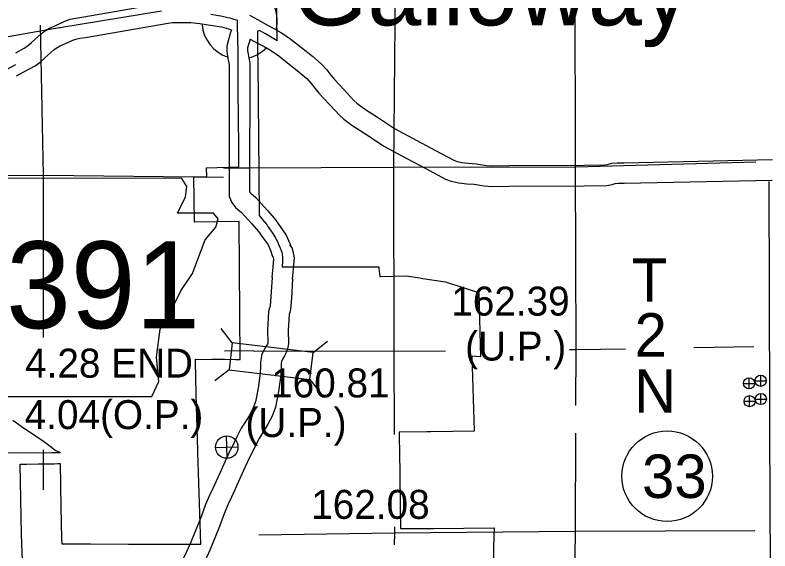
# Model space of a CAD drawing. Extents: x 1127717 to 1741049, y 2026793 to 2244711.
# Drawn here: x 1242222 to 1247728, y 2133375 to 2137280 of the extents above; entities that cross this region are included whole.
import ezdxf

# ---------------------------------------------------------------- set-up
doc = ezdxf.new("R2010")
doc.units = 0
for name, color, linetype in [('10', 7, 'Continuous'), ('15', 7, 'Continuous'), ('2', 7, 'Continuous'), ('20', 7, 'Continuous'), ('21', 7, 'Continuous'), ('24', 7, 'Continuous'), ('25', 7, 'Continuous'), ('26', 7, 'Continuous'), ('27', 7, 'Continuous'), ('30', 7, 'Continuous'), ('5', 7, 'Continuous'), ('58', 7, 'Continuous'), ('6', 7, 'Continuous')]:
    doc.layers.add(name, color=color, linetype=linetype)

msp = doc.modelspace()

# ---------------------------------------------------------------- linework, layer by layer
at = {"layer": '10'}
for points in [[(1243799.9, 2137173.2), (1243794.3, 2137152.9), (1243770.9, 2137074.7), (1243766.7, 2137050), (1243766.2, 2137021.9), (1243768.5, 2136998.8), (1243772.1, 2136979.4), (1243783.7, 2136915.3)], [(1243936.6, 2137105.4), (1243917.3, 2137040.6), (1243916.5, 2137035.9), (1243916.3, 2137027.9), (1243917.1, 2137020), (1243919.6, 2137006.5), (1243933.7, 2136928.7)], [(1243933.7, 2136928.7), (1243932.5, 2135992)], [(1243783.7, 2136915.3), (1243782.5, 2135957.4)], [(1243932.5, 2135992), (1243932.4, 2135992.3), (1243940.7, 2135981.2), (1243977.1, 2135949.5), (1244060.5, 2135858.8), (1244114.3, 2135797.2), (1244156.6, 2135739.2), (1244200, 2135677.1), (1244226.1, 2135614.4), (1244235.4, 2135589.3)], [(1243782.5, 2135957.4), (1243804, 2135913.5), (1243830.3, 2135878.5), (1243872.2, 2135841.9), (1243948.8, 2135758.7), (1243997, 2135703.5), (1244034.5, 2135652), (1244067.8, 2135604.5), (1244086.5, 2135559.5), (1244098.2, 2135528)], [(1244246.4, 2135356.2), (1244253.3, 2135430.6), (1244259.2, 2135510.7), (1244252.8, 2135548.2), (1244242, 2135584), (1244226.6, 2135606.1)], [(1244097, 2135370.1), (1244103.8, 2135443.1), (1244108.3, 2135503.5), (1244106.5, 2135513.8), (1244105.3, 2135517.8), (1244098.2, 2135528)], [(1244096.9, 2135368.2), (1244087.4, 2135228.9), (1244081.5, 2135157.3), (1244081.3, 2135156.2), (1244074.9, 2135140.9), (1244070.7, 2135116.2), (1244063.1, 2134986.6), (1244065.9, 2134894.4), (1244064.8, 2134888.7), (1244062.3, 2134882.4), (1244054.5, 2134866.7), (1244039.6, 2134840.7), (1244021.8, 2134808), (1244016.7, 2134780.2), (1244013, 2134749.3), (1244011.8, 2134720.8)], [(1244246.5, 2135358), (1244237, 2135217.6), (1244230.3, 2135136.2), (1244225.4, 2135112), (1244219.9, 2135098.9), (1244213.2, 2134984.4), (1244216.3, 2134883.1), (1244209.8, 2134847.4), (1244199.4, 2134821.1), (1244186.8, 2134795.8), (1244170.6, 2134767.6), (1244165, 2134757.3), (1244162.6, 2134737.2), (1244161.6, 2134714.4)], [(1244011.8, 2134720.8), (1244009.6, 2134669.8), (1243994.1, 2134560.9), (1243975.7, 2134461.3), (1243959.4, 2134417.6), (1243935.6, 2134371.4), (1243904.6, 2134321.3), (1243872, 2134269.3), (1243841.4, 2134211.4), (1243797.1, 2134119.5)], [(1244161.6, 2134714.4), (1244159.2, 2134656), (1244142.2, 2134536.7), (1244120.8, 2134421.2), (1244096.8, 2134356.8), (1244066.2, 2134297.5), (1244031.9, 2134242), (1244002, 2134194.3), (1243975.3, 2134143.7), (1243932.2, 2134054.3)], [(1243796.5, 2134118.3), (1243764.8, 2134049.6), (1243714.8, 2133942.5), (1243687.8, 2133882.9), (1243663.1, 2133830.1), (1243636.1, 2133769.8), (1243611.9, 2133713.8), (1243590.8, 2133656.1), (1243573.1, 2133605.1), (1243504.7, 2133439.6), (1243456.7, 2133335.2), (1243439.3, 2133301.6), (1243428.4, 2133270.6), (1243412, 2133204.1), (1243332.4, 2132858.6)], [(1243932.7, 2134055.5), (1243900.9, 2133986.5), (1243851.1, 2133879.9), (1243824.1, 2133820.1), (1243799.5, 2133767.6), (1243773.4, 2133709.4), (1243751.3, 2133658.2), (1243732.1, 2133605.8), (1243713.4, 2133551.8), (1243642.2, 2133379.6), (1243591.5, 2133269.3), (1243577.4, 2133242.1), (1243572.4, 2133227.7), (1243557.9, 2133169.2), (1243485.6, 2132855.4)]]:
    msp.add_lwpolyline(points, dxfattribs=at)
at = {"layer": '15'}
for points in [[(1242228.1, 2137005.3), (1242288.1, 2137037.9), (1242295.6, 2137043.4), (1242309.9, 2137054.3), (1242340.9, 2137080.9), (1242411, 2137142.8), (1242436.4, 2137161.8), (1242474, 2137185.2), (1242527.7, 2137209.9), (1242585.3, 2137234.9), (1242622.7, 2137249.3), (1242665.9, 2137258.2), (1242709.8, 2137265.5), (1243312.7, 2137368.1), (1243354.8, 2137376), (1243395.8, 2137376.8), (1243435.9, 2137376.7), (1243515.2, 2137374.8), (1243587.7, 2137366.3), (1243682.5, 2137353), (1243757.1, 2137342.3), (1243777.3, 2137336.7)], [(1243931.1, 2137279.2), (1243941, 2137274.1), (1244012.1, 2137235), (1244067.2, 2137204.6), (1244109.6, 2137182), (1244160.2, 2137153.9)], [(1242231.6, 2136837.4), (1242280.5, 2136863.1), (1242368.8, 2136911), (1242385.7, 2136923.4), (1242404.4, 2136937.8), (1242439.3, 2136967.8), (1242505.7, 2137026.3), (1242521.2, 2137037.9), (1242545.2, 2137052.9), (1242588.8, 2137072.9), (1242642.3, 2137096.1), (1242665.1, 2137104.9), (1242693.2, 2137110.7), (1242734.7, 2137117.5), (1243339, 2137220.4), (1243370.3, 2137226.3), (1243397.2, 2137226.8), (1243433.9, 2137226.7), (1243504.6, 2137225), (1243568.5, 2137217.5), (1243661.4, 2137204.5), (1243726.4, 2137195.2), (1243779.2, 2137180.6), (1243797.5, 2137174.3)], [(1244160.2, 2137153.9), (1244222.9, 2137112.1), (1244311.3, 2137043.5), (1244391.2, 2136979.4), (1244454.7, 2136924.1), (1244494.6, 2136879.8), (1244524.8, 2136842.6), (1244551.1, 2136810.5), (1244585.9, 2136773.4), (1244623.6, 2136733.3), (1244668.3, 2136685.2), (1244692, 2136658.3), (1244714.9, 2136638.2), (1244764.2, 2136601.4), (1244880.9, 2136525.5), (1244988.9, 2136454.4), (1245151.1, 2136366.3), (1245288.3, 2136293.5), (1245423.3, 2136221.6), (1245446.2, 2136212.7), (1245481.4, 2136204.8), (1245530, 2136200), (1245586.5, 2136196.4), (1245661.2, 2136184.1), (1245706.4, 2136180.7), (1245822.5, 2136182.7), (1246373.5, 2136185.9), (1246521.7, 2136187.5), (1246542.4, 2136192), (1246574.6, 2136200), (1246614.2, 2136203.7), (1246661.3, 2136204.1), (1247745.5, 2136227)], [(1243936.6, 2137105.4), (1243995.7, 2137072.8), (1244037.8, 2137050.3), (1244084.6, 2137024.3)], [(1244079.5, 2137027.4), (1244135.2, 2136990.2), (1244218.4, 2136925.7), (1244295, 2136864.3), (1244349.3, 2136816.9), (1244380.6, 2136782.2), (1244408.5, 2136747.9), (1244438.2, 2136711.6), (1244476.6, 2136670.7), (1244514, 2136630.9), (1244557.1, 2136584.5), (1244586, 2136551.8), (1244620.5, 2136521.5), (1244678.4, 2136478.3), (1244798.8, 2136400), (1244911.7, 2136325.6), (1245080.2, 2136234.2), (1245217.8, 2136161), (1245360.7, 2136085), (1245402.4, 2136068.8), (1245457.6, 2136056.4), (1245518, 2136050.4), (1245569.5, 2136047.2), (1245643.3, 2136035), (1245702.1, 2136030.6), (1245824.3, 2136032.7), (1246374.7, 2136035.9), (1246538.7, 2136037.7), (1246576.5, 2136045.9), (1246599.8, 2136051.7), (1246621.9, 2136053.8), (1246663.5, 2136054.1), (1247745, 2136077)], [(1242020.6, 2136811.2), (1242227.5, 2136920)]]:
    msp.add_lwpolyline(points, dxfattribs=at)
at = {"layer": '2'}
msp.add_lwpolyline([(1247719.9, 2136068.2), (1247726, 2133591.9), (1247745.1, 2132243.6)], dxfattribs=at)
at = {"layer": '20'}
for p, q in [((1243806.5, 2134891.8), (1243724.9, 2134995.6)), ((1244396.2, 2134821), (1244500, 2134902.6)), ((1243782.9, 2134695.2), (1243679.1, 2134613.6)), ((1244372.7, 2134624.4), (1244454.2, 2134520.6))]:
    msp.add_line(p, q, dxfattribs=at)
msp.add_lwpolyline([(1243782.9, 2134695.2), (1244372.7, 2134624.4), (1244396.2, 2134821), (1243806.5, 2134891.8)], close=True, dxfattribs=at)
at = {"layer": '21'}
msp.add_lwpolyline([(1241917.3, 2136090.2), (1241993.5, 2135582.7), (1241959.6, 2134812.9), (1242027.3, 2134770.6), (1242154.2, 2134770.6), (1242154.2, 2134500), (1243220, 2134500), (1243270.8, 2134609.9), (1243253.9, 2134787.6), (1243279.2, 2134990.6), (1243372.3, 2135151.3), (1243431.5, 2135269.7), (1243516.1, 2135396.6), (1243566.8, 2135532), (1243609.1, 2135641.9), (1243685.3, 2135735), (1243702.2, 2135794.2), (1243668.3, 2135836.5), (1243406.1, 2135836.5), (1243465.3, 2135954.9), (1243473.8, 2136031), (1243438.7, 2136089.5)], close=True, dxfattribs=at)
at = {"layer": '24'}
for start, end in [(346.4695, 74.2639), (185.0338, 252.1304), (284.5564, 315.4275)]:
    msp.add_arc((1243859.3, 2137235), 275, start, end, dxfattribs=at)
at = {"layer": '26'}
for p, q in [((1247576.1, 2134555.3), (1247576.1, 2134636.6)), ((1247619.8, 2134614.6), (1247701.1, 2134614.6)), ((1247660.5, 2134574), (1247660.5, 2134655.2)), ((1247535.5, 2134596), (1247616.7, 2134596)), ((1247579.5, 2134425.2), (1247579.5, 2134506.5)), ((1247661.6, 2134440.6), (1247661.6, 2134521.8)), ((1247538.9, 2134465.9), (1247620.1, 2134465.9)), ((1247621, 2134481.2), (1247702.3, 2134481.2)), ((1243768.2, 2134049.9), (1243764.5, 2134212.6)), ((1243685, 2134129.4), (1243847.7, 2134133.1))]:
    msp.add_line(p, q, dxfattribs=at)
for centre, radius in [((1247576.1, 2134596), 40.6), ((1247660.5, 2134614.6), 40.6), ((1247579.5, 2134465.9), 40.6), ((1247661.6, 2134481.2), 40.6), ((1243766.3, 2134131.2), 81.4)]:
    msp.add_circle(centre, radius, dxfattribs=at)
at = {"layer": '27'}
msp.add_circle((1246978.1, 2133919), 330, dxfattribs=at)
at = {"layer": '5'}
for points in [[(1245008.2, 2138758.5), (1244993.1, 2137486.7), (1244981.8, 2136170.8), (1244985.7, 2134830.4), (1244987.2, 2134223.4)], [(1246313.2, 2134435.1), (1246314.3, 2134845.1), (1246309.2, 2136177.5), (1246308.4, 2137514), (1246311.7, 2138782.2)], [(1242429.3, 2134929.9), (1242429.9, 2136113.8), (1242407.7, 2137206.9)], [(1243928.1, 2136165.8), (1244980.3, 2136171.3), (1246311.3, 2136174), (1247623.8, 2136209.8)], [(1243742.4, 2136165.5), (1243928.1, 2136165.8)], [(1242116.8, 2136109.8), (1242431.9, 2136112.4), (1243742.8, 2136098.3)], [(1243960.4, 2134831.9), (1243748.6, 2134831.7)], [(1243960.4, 2134831.9), (1244988.1, 2134831), (1245360.5, 2134834.1)], [(1246264.8, 2134841.7), (1246314.9, 2134842.1), (1246674.9, 2134848.5)], [(1247173.9, 2134857.5), (1247609.4, 2134865.3)], [(1243748.3, 2134770), (1243656.4, 2134770.6)], [(1246292.8, 2132227), (1246310.7, 2133522), (1246312.6, 2134233)], [(1242430.3, 2133819.3), (1242430, 2134111.2)], [(1244000.8, 2133492.3), (1244988.6, 2133507), (1246310.8, 2133519), (1247618.8, 2133523)], [(1244989, 2133549.9), (1244989.1, 2133505), (1244986.7, 2133418.3)]]:
    msp.add_lwpolyline(points, dxfattribs=at)
at = {"layer": '6'}
for points in [[(1244126.3, 2137443.3), (1244132.2, 2137101.1), (1244132.2, 2137099.6), (1244132.3, 2137097.9), (1244132.4, 2137091.9), (1244047.8, 2137142.7), (1244004, 2137168), (1243999.6, 2137166.1), (1243996.5, 2137164.8), (1243993.3, 2137163.3), (1243990.6, 2137162.2), (1243989.2, 2137161.6), (1243990.7, 2137009.4), (1243991.4, 2136933.7), (1243991.5, 2136932.1), (1243991.5, 2136930.4), (1243999.4, 2136119.7), (1244000.5, 2136034.4), (1244000.6, 2136032.9), (1244000.6, 2136031.4), (1244000.9, 2136006.6), (1244000.9, 2136004.7), (1244001, 2136003), (1244001.9, 2135929.8), (1244002.9, 2135857.6), (1244003, 2135849.9), (1244003.4, 2135818.1), (1244003.5, 2135815.8), (1244023.9, 2135791.8), (1244026, 2135789.3), (1244040.9, 2135771.9), (1244042.7, 2135769.9), (1244050.9, 2135760.5), (1244057.9, 2135751.8), (1244060.2, 2135748.9), (1244066.6, 2135739.4), (1244072.9, 2135730.3), (1244094.8, 2135697.3), (1244101.6, 2135686.9), (1244108.1, 2135677), (1244122.8, 2135652.3), (1244126.4, 2135645.7), (1244137.2, 2135625.7), (1244142, 2135616), (1244150.6, 2135594.5), (1244153.2, 2135589), (1244158.3, 2135575.9), (1244158.6, 2135575.1), (1244163, 2135563.3), (1244166.8, 2135552), (1244166.9, 2135551.4), (1244170.4, 2135536.5), (1244172.4, 2135513.8), (1244172.2, 2135487.6), (1244170, 2135445.4), (1244174.8, 2135445.4), (1244176.9, 2135445.4), (1244179, 2135445.4), (1244874.6, 2135445.8), (1244875.8, 2135434.1), (1244882.1, 2135374.2), (1244886.3, 2135374.3), (1245073.3, 2135379.9), (1245074.4, 2135379.7), (1245174.4, 2135364.3), (1245194.5, 2135361.2), (1245195.6, 2135361), (1245196.8, 2135360.8), (1245361.7, 2135335.3), (1245373.3, 2135331.6), (1245383.7, 2135328.2), (1245391.7, 2135325.6), (1245603.2, 2135257.4), (1245603.5, 2135247.3), (1245617.2, 2134789.6), (1245553.3, 2134793), (1245570.4, 2134250), (1245570.5, 2134247.6), (1245255, 2134243.4), (1245247.1, 2134243.2), (1245244.2, 2134243.2), (1245244.1, 2134243.2), (1245241.5, 2134243.2), (1245238.8, 2134243.1), (1245235.2, 2134243.1), (1245232.7, 2134243)], [(1242286.2, 2133042.6), (1242269.8, 2133496.4), (1242260.1, 2134007.3), (1242307.6, 2134007.9), (1242390.9, 2134009), (1242458.6, 2134009.8), (1242492.5, 2134010.2), (1242498.4, 2134010.3), (1242506.3, 2134010.4), (1242531.6, 2134010.7), (1242550.8, 2134011.9), (1242556.3, 2133693), (1242560.2, 2133465), (1242562.1, 2133427.2), (1242774.1, 2133426.1), (1243049.6, 2133424.7), (1243082.7, 2133424.5), (1243166.1, 2133424.1), (1243182.3, 2133424.2), (1243520.2, 2133424.4), (1243576.2, 2133424.4), (1243554.1, 2134093.8), (1243554.1, 2134095.7), (1243553.9, 2134100.9), (1243553.9, 2134101.5), (1243553.8, 2134102.7), (1243553.8, 2134105.5), (1243543.5, 2134515), (1243537.3, 2134759.5), (1243537, 2134772.3), (1243539, 2134772.3), (1243541.3, 2134772.3), (1243830.5, 2134770.8), (1243852.4, 2134770.7), (1243864.7, 2134770.6), (1243857, 2135776.6), (1243529.7, 2135771.5), (1243526.1, 2136101.8), (1243619.6, 2136103.2), (1243617.7, 2136165.9), (1243854, 2136172.8), (1243852.9, 2136309.2), (1243851.2, 2136537.4), (1243851.2, 2136539.4), (1243851.2, 2136541.7), (1243849.8, 2136715.9), (1243849.5, 2136945.1), (1243849.5, 2136956.3), (1243849.4, 2136959.3), (1243849.2, 2136974.4), (1243848.9, 2136991.8), (1243848.9, 2136993.1), (1243848.9, 2136994.5), (1243848.7, 2137005.1), (1243848, 2137054.7), (1243847.8, 2137064.3), (1243847.7, 2137072.6), (1243845.1, 2137238), (1243845.1, 2137239.6), (1243813.5, 2137250.1), (1243799.1, 2137254.9), (1243793.2, 2137256.9), (1243773.3, 2137261), (1243721.9, 2137271.7), (1243706.2, 2137274.9), (1243649.9, 2137285.1)], [(1243290.5, 2137307.9), (1242563.2, 2137189.1)], [(1242563.2, 2137189.1), (1242553.4, 2137187.4), (1242548.9, 2137186.6), (1242544.6, 2137185.9), (1241880.4, 2137070.3), (1241874.6, 2137069.3), (1241874.8, 2137036.7)], [(1242206.1, 2134328.5), (1242266.7, 2134283.9), (1242428.3, 2134175.1), (1242449.6, 2134158.8), (1242487.8, 2134129.9), (1242514.3, 2134109.7), (1242551.2, 2134093), (1242551.2, 2134092.7), (1242551.2, 2134088.9), (1242507.9, 2134089.3), (1242490, 2134089.2), (1241951.4, 2134086.4)], [(1245232.7, 2134243), (1245229.9, 2134243), (1245227.5, 2134243), (1245226.7, 2134243), (1245224.8, 2134242.9), (1245023.3, 2134240.2), (1245023.4, 2134235.7), (1245023.4, 2134233.5), (1245023.6, 2134218.2), (1245024.2, 2134173.5), (1245025, 2134117.9), (1245025, 2134114.7), (1245025.1, 2134108.5), (1245032.7, 2133538.6), (1245275, 2133537.6), (1245715.7, 2133542.5), (1245712.4, 2133402.4), (1245712.4, 2133400.7), (1245712.3, 2133398.7), (1245710.6, 2133323.5)]]:
    msp.add_lwpolyline(points, dxfattribs=at)

# ---------------------------------------------------------------- texts
at = {"layer": '21'}
msp.add_text('391', height=633.6, dxfattribs=at).set_placement((1242157.1, 2134997.2))
at = {"layer": '24'}
msp.add_text('Galloway', height=528, dxfattribs=at).set_placement((1244242.7, 2137205.4))
at = {"layer": '25'}
msp.add_text('4.28 END', height=211.2, dxfattribs=at).set_placement((1242294.9, 2134637.6))
at = {"layer": '27'}
msp.add_text('33', height=316.8, dxfattribs=at).set_placement((1246795.1, 2133760.6))
at = {"layer": '30'}
for s, p in [('T', (1246720.4, 2135190.1)), ('2', (1246740.6, 2134790.9)), ('N', (1246737.3, 2134381.4))]:
    msp.add_text(s, height=316.8, dxfattribs=at).set_placement(p)
at = {"layer": '58'}
for s, p in [('162.39', (1245403.3, 2135089.7)), ('(U.P.)', (1245504.7, 2134762.2)), ('160.81', (1244089.6, 2134493.3)), ('4.04(O.P.)', (1242291.9, 2134262.3)), ('(U.P.)', (1243902.4, 2134204.8)), ('162.08', (1244381.9, 2133608.3))]:
    msp.add_text(s, height=211.2, dxfattribs=at).set_placement(p)

doc.saveas('drawing.dxf')
